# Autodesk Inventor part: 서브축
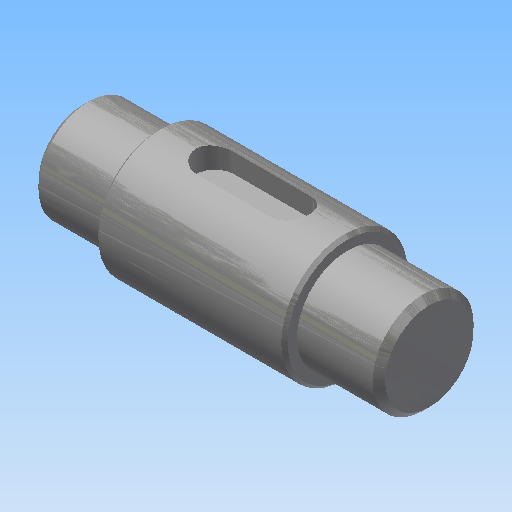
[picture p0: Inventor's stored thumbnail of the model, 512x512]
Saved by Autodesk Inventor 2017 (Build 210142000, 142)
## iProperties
Created: 2019-03
Part Number: 서브축
Material: 강철, 연강
Document SubType Name: Modeling
Designer: mduedu
Density: 1 g/cm^3
Appearance: 강철
Author: mduedu
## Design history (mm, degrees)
sketch "스케치1"
  geometry: L1 (0, 0)-(12, 0); L2 (12, 0)-(12, 8); L3 (12, 8)-(0, 8); L4 (0, 8)-(0, 0); L5 (12, 0)-(42, 0); L6 (42, 0)-(42, 10); L7 (42, 10)-(12, 10); L8 (12, 10)-(12, 0); L9 (42, 0)-(55, 0); L10 (55, 0)-(55, 8); L11 (55, 8)-(42, 8); L12 (42, 8)-(42, 0)
  constraints: 24 end point, 6 parallel, 3 horizontal, 3 perpendicular
  dimensions: "d0" = 16 diameter of L3 L1; "d2" = 20 diameter of L7 L5; "d3" = 16 diameter of L11 L9; "d4" = 12 distance of L2.end L3.end; "d5" = 30 distance of L6.end L7.end; "d6" = 55 distance between parallel lines of L10 L4
revolve "회전1" sketch "스케치1" stored, may be unused: angle "d7" = 90 deg
node "작업 평면1"
sketch "스케치2" dims "d10" = 18
  geometry: L1 (6, -3)-(-6, -3); L2 (-6, -3)-(-6, 3); L3 (-6, 3)-(6, 3); L4 (6, 3)-(6, -3); L5 (15, 10)-(15, -10) reference; 3 further points
  constraints: 8 end point, 2 midpoint, 2 parallel, 2 vertical alignment, 1 horizontal, 1 horizontal alignment, 1 perpendicular, 4 other
  dimensions: "d8" = 6 distance between parallel lines of L3 L1; "d11" = 6 dimension on L5
extrude "돌출1" cut sketch "스케치2" distance "d12" = 3.5; taper "d13" = 0 deg
chamfer "모따기1" distance "d14" = 1; stored, may be unused: second distance "d15" = 2, angle "d16" = 45 deg
chamfer "모따기2" distance "d17" = 0.5; stored, may be unused: second distance "d18" = 2, angle "d19" = 45 deg
node "솔리드1"
